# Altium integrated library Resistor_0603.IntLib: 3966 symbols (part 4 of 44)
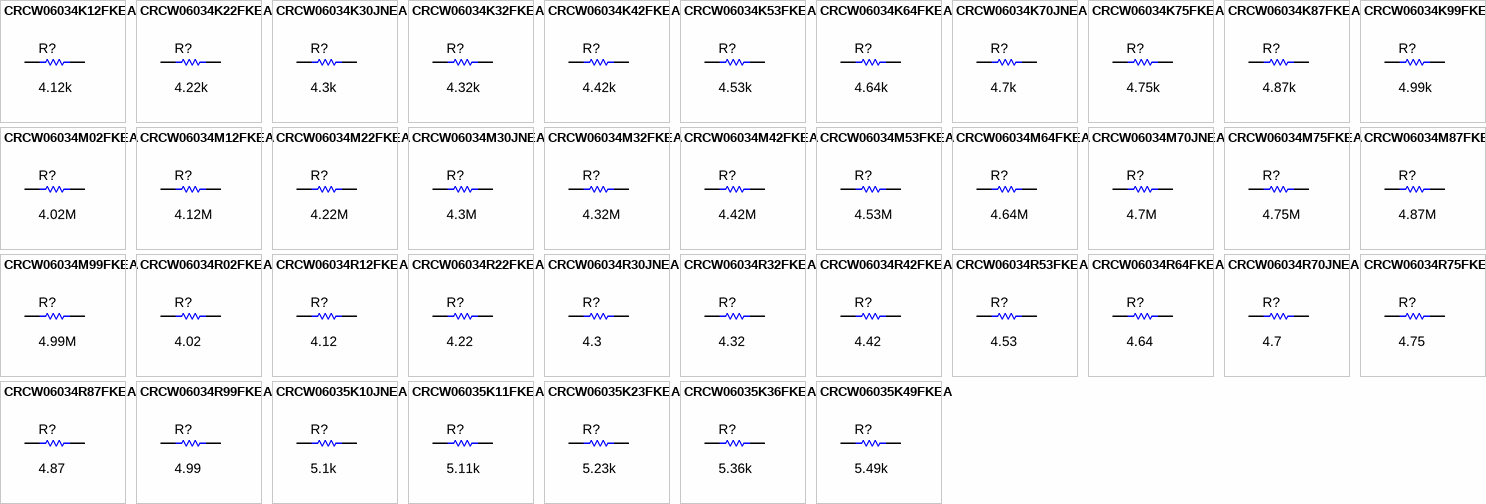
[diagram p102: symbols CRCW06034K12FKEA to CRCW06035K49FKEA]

## CRCW06034R42FKEA
designator R?  ValueDisplayed: 4.42  (hidden comment: CRCW06034R42FKEA)
RES, 4.42, 1%, 0.1 W, 0603; Manufacturer: Vishay-Dale; CompType: Resistor; Value: 4.42; Value_Code: 4R42; Tolerance_%: 1; Power_W: 0.1; Value2: 0.1W; VDC_V: 75; TempCo: 100 ppm/C; SizeArea_mm2: 1.28; SizeX_mm: 1.6; SizeY_mm: 0.8; EIA_Code: E96; U/M: EA; AEC Category: Q200
signal-integrity model Resistor
simulation model Resistor
footprint 0603
footprint 0603M
footprint 0603L
footprint 0603_HV
footprint 0603S
pins: 1, 2

## CRCW06034R53FKEA
designator R?  ValueDisplayed: 4.53  (hidden comment: CRCW06034R53FKEA)
RES, 4.53, 1%, 0.1 W, 0603; Manufacturer: Vishay-Dale; CompType: Resistor; Value: 4.53; Value_Code: 4R53; Tolerance_%: 1; Power_W: 0.1; Value2: 0.1W; VDC_V: 75; TempCo: 100 ppm/C; SizeArea_mm2: 1.28; SizeX_mm: 1.6; SizeY_mm: 0.8; EIA_Code: E96; U/M: EA; AEC Category: Q200
signal-integrity model Resistor
simulation model Resistor
footprint 0603
footprint 0603M
footprint 0603L
footprint 0603_HV
footprint 0603S
pins: 1, 2

## CRCW06034R64FKEA
designator R?  ValueDisplayed: 4.64  (hidden comment: CRCW06034R64FKEA)
RES, 4.64, 1%, 0.1 W, 0603; Manufacturer: Vishay-Dale; CompType: Resistor; Value: 4.64; Value_Code: 4R64; Tolerance_%: 1; Power_W: 0.1; Value2: 0.1W; VDC_V: 75; TempCo: 100 ppm/C; SizeArea_mm2: 1.28; SizeX_mm: 1.6; SizeY_mm: 0.8; EIA_Code: E96; U/M: EA; AEC Category: Q200
signal-integrity model Resistor
simulation model Resistor
footprint 0603
footprint 0603M
footprint 0603L
footprint 0603_HV
footprint 0603S
pins: 1, 2

## CRCW06034R70JNEA
designator R?  ValueDisplayed: 4.7  (hidden comment: CRCW06034R70JNEA)
RES, 4.7, 5%, 0.1 W, 0603; Manufacturer: Vishay-Dale; CompType: Resistor; Value: 4.7; Value_Code: 4R70; Tolerance_%: 5; Power_W: 0.1; Value2: 0.1W; VDC_V: 75; TempCo: 200 ppm/C; SizeArea_mm2: 1.28; SizeX_mm: 1.6; SizeY_mm: 0.8; SizeZ_mm: 1; EIA_Code: E24; U/M: EA; AEC Category: Q200; Green_Lifecycle: Active; Green_REACh: Passed
signal-integrity model Resistor
simulation model Resistor
footprint 0603
footprint 0603M
footprint 0603L
footprint 0603_HV
footprint 0603S
pins: 1, 2

## CRCW06034R75FKEA
designator R?  ValueDisplayed: 4.75  (hidden comment: CRCW06034R75FKEA)
RES, 4.75, 1%, 0.1 W, 0603; Manufacturer: Vishay-Dale; CompType: Resistor; Value: 4.75; Value_Code: 4R75; Tolerance_%: 1; Power_W: 0.1; Value2: 0.1W; VDC_V: 75; TempCo: 100 ppm/C; SizeArea_mm2: 1.28; SizeX_mm: 1.6; SizeY_mm: 0.8; EIA_Code: E96; U/M: EA; AEC Category: Q200; Green_Lifecycle: Active; Green_REACh: Passed
signal-integrity model Resistor
simulation model Resistor
footprint 0603
footprint 0603M
footprint 0603L
footprint 0603_HV
footprint 0603S
pins: 1, 2

## CRCW06034R87FKEA
designator R?  ValueDisplayed: 4.87  (hidden comment: CRCW06034R87FKEA)
RES, 4.87, 1%, 0.1 W, 0603; Manufacturer: Vishay-Dale; CompType: Resistor; Value: 4.87; Value_Code: 4R87; Tolerance_%: 1; Power_W: 0.1; Value2: 0.1W; VDC_V: 75; TempCo: 100 ppm/C; SizeArea_mm2: 1.28; SizeX_mm: 1.6; SizeY_mm: 0.8; EIA_Code: E96; U/M: EA; AEC Category: Q200; Green_Lifecycle: Active; Green_REACh: Passed
signal-integrity model Resistor
simulation model Resistor
footprint 0603
footprint 0603M
footprint 0603L
footprint 0603_HV
footprint 0603S
pins: 1, 2

## CRCW06034R99FKEA
designator R?  ValueDisplayed: 4.99  (hidden comment: CRCW06034R99FKEA)
RES, 4.99, 1%, 0.1 W, 0603; Manufacturer: Vishay-Dale; CompType: Resistor; Value: 4.99; Value_Code: 4R99; Tolerance_%: 1; Power_W: 0.1; Value2: 0.1W; VDC_V: 75; TempCo: 100 ppm/C; SizeArea_mm2: 1.28; SizeX_mm: 1.6; SizeY_mm: 0.8; EIA_Code: E96; U/M: EA; AEC Category: Q200; Green_Lifecycle: Active; Green_REACh: Passed
signal-integrity model Resistor
simulation model Resistor
footprint 0603
footprint 0603M
footprint 0603L
footprint 0603_HV
footprint 0603S
pins: 1, 2

## CRCW06035K10JNEA
designator R?  ValueDisplayed: 5.1k  (hidden comment: CRCW06035K10JNEA)
RES, 5.1 k, 5%, 0.1 W, 0603; Manufacturer: Vishay-Dale; CompType: Resistor; Value: 5.1k; Res_ohm: 5100; Value_Code: 5k10; Tolerance_%: 5; Power_W: 0.1; Value2: 0.1W; VDC_V: 75; TempCo: 200 ppm/C; SizeArea_mm2: 1.28; SizeX_mm: 1.6; SizeY_mm: 0.8; SizeZ_mm: 1; EIA_Code: E24; U/M: EA; AEC Category: Q200; Green_Lifecycle: Active; Green_REACh: Passed
signal-integrity model Resistor
simulation model Resistor
footprint 0603
footprint 0603M
footprint 0603L
footprint 0603_HV
footprint 0603S
pins: 1, 2

## CRCW06035K11FKEA
designator R?  ValueDisplayed: 5.11k  (hidden comment: CRCW06035K11FKEA)
RES, 5.11 k, 1%, 0.1 W, 0603; Manufacturer: Vishay-Dale; CompType: Resistor; Value: 5.11k; Res_ohm: 5110; Value_Code: 5k11; Tolerance_%: 1; Power_W: 0.1; Value2: 0.1W; VDC_V: 75; TempCo: 100 ppm/C; SizeArea_mm2: 1.28; SizeX_mm: 1.6; SizeY_mm: 0.8; EIA_Code: E96; U/M: EA; AEC Category: Q200; Green_Lifecycle: Active; Green_REACh: Passed
signal-integrity model Resistor
simulation model Resistor
footprint 0603
footprint 0603M
footprint 0603L
footprint 0603_HV
footprint 0603S
pins: 1, 2

## CRCW06035K23FKEA
designator R?  ValueDisplayed: 5.23k  (hidden comment: CRCW06035K23FKEA)
RES, 5.23 k, 1%, 0.1 W, 0603; Manufacturer: Vishay-Dale; CompType: Resistor; Value: 5.23k; Res_ohm: 5230; Value_Code: 5k23; Tolerance_%: 1; Power_W: 0.1; Value2: 0.1W; VDC_V: 75; TempCo: 100 ppm/C; SizeArea_mm2: 1.28; SizeX_mm: 1.6; SizeY_mm: 0.8; EIA_Code: E96; U/M: EA; AEC Category: Q200; Green_Lifecycle: Active; Green_REACh: Passed
signal-integrity model Resistor
simulation model Resistor
footprint 0603
footprint 0603M
footprint 0603L
footprint 0603_HV
footprint 0603S
pins: 1, 2

## CRCW06035K36FKEA
designator R?  ValueDisplayed: 5.36k  (hidden comment: CRCW06035K36FKEA)
RES, 5.36 k, 1%, 0.1 W, 0603; Manufacturer: Vishay-Dale; CompType: Resistor; Value: 5.36k; Res_ohm: 5360; Value_Code: 5k36; Tolerance_%: 1; Power_W: 0.1; Value2: 0.1W; VDC_V: 75; TempCo: 100 ppm/C; SizeArea_mm2: 1.28; SizeX_mm: 1.6; SizeY_mm: 0.8; EIA_Code: E96; U/M: EA; AEC Category: Q200; Green_Lifecycle: Active; Green_REACh: Passed
signal-integrity model Resistor
simulation model Resistor
footprint 0603
footprint 0603M
footprint 0603L
footprint 0603_HV
footprint 0603S
pins: 1, 2

## CRCW06035K49FKEA
designator R?  ValueDisplayed: 5.49k  (hidden comment: CRCW06035K49FKEA)
RES, 5.49 k, 1%, 0.1 W, 0603; Manufacturer: Vishay-Dale; CompType: Resistor; Value: 5.49k; Res_ohm: 5490; Value_Code: 5k49; Tolerance_%: 1; Power_W: 0.1; Value2: 0.1W; VDC_V: 75; TempCo: 100 ppm/C; SizeArea_mm2: 1.28; SizeX_mm: 1.6; SizeY_mm: 0.8; EIA_Code: E96; U/M: EA; AEC Category: Q200; Green_Lifecycle: Active; Green_REACh: Passed
signal-integrity model Resistor
simulation model Resistor
footprint 0603
footprint 0603M
footprint 0603L
footprint 0603_HV
footprint 0603S
pins: 1, 2

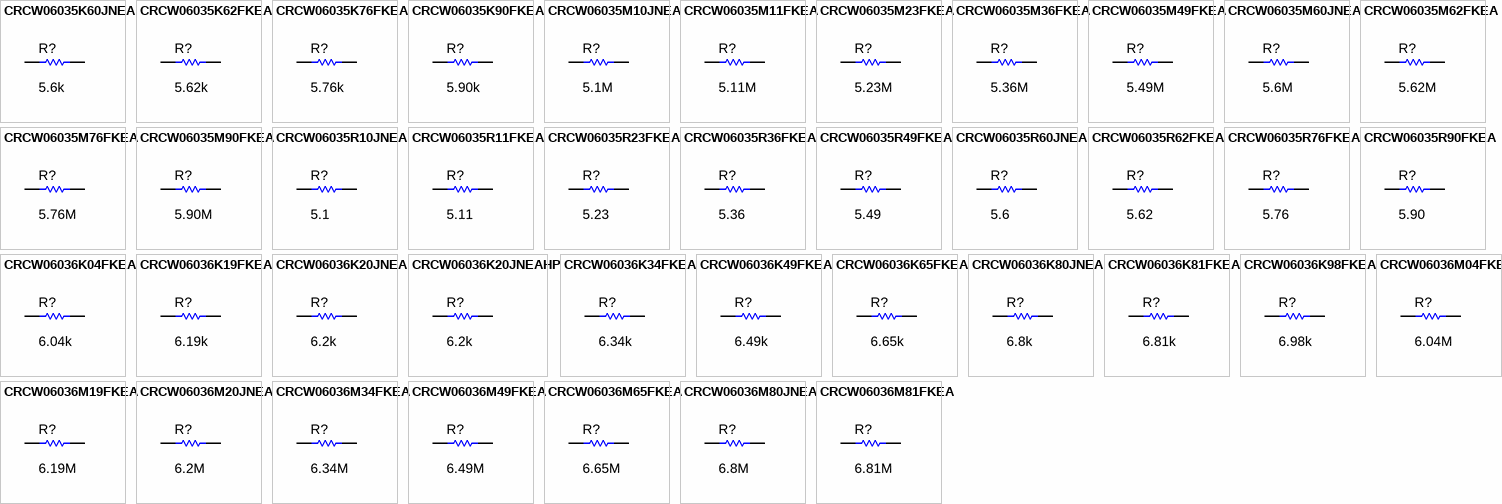
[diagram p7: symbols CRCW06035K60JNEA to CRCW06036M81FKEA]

## CRCW06035K60JNEA
designator R?  ValueDisplayed: 5.6k  (hidden comment: CRCW06035K60JNEA)
RES, 5.6 k, 5%, 0.1 W, 0603; Manufacturer: Vishay-Dale; CompType: Resistor; Value: 5.6k; Res_ohm: 5600; Value_Code: 5k60; Tolerance_%: 5; Power_W: 0.1; Value2: 0.1W; VDC_V: 75; TempCo: 200 ppm/C; SizeArea_mm2: 1.28; SizeX_mm: 1.6; SizeY_mm: 0.8; SizeZ_mm: 1; EIA_Code: E24; U/M: EA; AEC Category: Q200; Green_Lifecycle: Active; Green_REACh: Passed
signal-integrity model Resistor
simulation model Resistor
footprint 0603
footprint 0603M
footprint 0603L
footprint 0603_HV
footprint 0603S
pins: 1, 2

## CRCW06035K62FKEA
designator R?  ValueDisplayed: 5.62k  (hidden comment: CRCW06035K62FKEA)
RES, 5.62 k, 1%, 0.1 W, 0603; Manufacturer: Vishay-Dale; CompType: Resistor; Value: 5.62k; Res_ohm: 5620; Value_Code: 5k62; Tolerance_%: 1; Power_W: 0.1; Value2: 0.1W; VDC_V: 75; TempCo: 100 ppm/C; SizeArea_mm2: 1.28; SizeX_mm: 1.6; SizeY_mm: 0.8; EIA_Code: E96; U/M: EA; AEC Category: Q200; Green_Lifecycle: Active; Green_REACh: Passed
signal-integrity model Resistor
simulation model Resistor
footprint 0603
footprint 0603M
footprint 0603L
footprint 0603_HV
footprint 0603S
pins: 1, 2

## CRCW06035K76FKEA
designator R?  ValueDisplayed: 5.76k  (hidden comment: CRCW06035K76FKEA)
RES, 5.76 k, 1%, 0.1 W, 0603; Manufacturer: Vishay-Dale; CompType: Resistor; Value: 5.76k; Res_ohm: 5760; Value_Code: 5k76; Tolerance_%: 1; Power_W: 0.1; Value2: 0.1W; VDC_V: 75; TempCo: 100 ppm/C; SizeArea_mm2: 1.28; SizeX_mm: 1.6; SizeY_mm: 0.8; EIA_Code: E96; U/M: EA; AEC Category: Q200; Green_Lifecycle: Active; Green_REACh: Passed
signal-integrity model Resistor
simulation model Resistor
footprint 0603
footprint 0603M
footprint 0603L
footprint 0603_HV
footprint 0603S
pins: 1, 2

## CRCW06035K90FKEA
designator R?  ValueDisplayed: 5.90k  (hidden comment: CRCW06035K90FKEA)
RES, 5.90 k, 1%, 0.1 W, 0603; Manufacturer: Vishay-Dale; CompType: Resistor; Value: 5.90k; Res_ohm: 5900; Value_Code: 5k90; Tolerance_%: 1; Power_W: 0.1; Value2: 0.1W; VDC_V: 75; TempCo: 100 ppm/C; SizeArea_mm2: 1.28; SizeX_mm: 1.6; SizeY_mm: 0.8; EIA_Code: E96; U/M: EA; AEC Category: Q200; Green_Lifecycle: Active; Green_REACh: Passed
signal-integrity model Resistor
simulation model Resistor
footprint 0603
footprint 0603M
footprint 0603L
footprint 0603_HV
footprint 0603S
pins: 1, 2

## CRCW06035M10JNEA
designator R?  ValueDisplayed: 5.1M  (hidden comment: CRCW06035M10JNEA)
RES, 5.1 M, 5%, 0.1 W, 0603; Manufacturer: Vishay-Dale; CompType: Resistor; Value: 5.1Meg; Res_ohm: 5100000; Value_Code: 5M10; Tolerance_%: 5; Power_W: 0.1; Value2: 0.1W; VDC_V: 75; TempCo: 200 ppm/C; SizeArea_mm2: 1.28; SizeX_mm: 1.6; SizeY_mm: 0.8; SizeZ_mm: 1; EIA_Code: E24; U/M: EA; AEC Category: Q200
signal-integrity model Resistor
simulation model Resistor
footprint 0603
footprint 0603M
footprint 0603L
footprint 0603_HV
footprint 0603S
pins: 1, 2

## CRCW06035M11FKEA
designator R?  ValueDisplayed: 5.11M  (hidden comment: CRCW06035M11FKEA)
RES, 5.11 M, 1%, 0.1 W, 0603; Manufacturer: Vishay-Dale; CompType: Resistor; Value: 5.11Meg; Res_ohm: 5110000; Value_Code: 5M11; Tolerance_%: 1; Power_W: 0.1; Value2: 0.1W; VDC_V: 75; TempCo: 100 ppm/C; SizeArea_mm2: 1.28; SizeX_mm: 1.6; SizeY_mm: 0.8; EIA_Code: E96; U/M: EA; AEC Category: Q200
signal-integrity model Resistor
simulation model Resistor
footprint 0603
footprint 0603M
footprint 0603L
footprint 0603_HV
footprint 0603S
pins: 1, 2

## CRCW06035M23FKEA
designator R?  ValueDisplayed: 5.23M  (hidden comment: CRCW06035M23FKEA)
RES, 5.23 M, 1%, 0.1 W, 0603; Manufacturer: Vishay-Dale; CompType: Resistor; Value: 5.23Meg; Res_ohm: 5230000; Value_Code: 5M23; Tolerance_%: 1; Power_W: 0.1; Value2: 0.1W; VDC_V: 75; TempCo: 100 ppm/C; SizeArea_mm2: 1.28; SizeX_mm: 1.6; SizeY_mm: 0.8; EIA_Code: E96; U/M: EA; AEC Category: Q200
signal-integrity model Resistor
simulation model Resistor
footprint 0603
footprint 0603M
footprint 0603L
footprint 0603_HV
footprint 0603S
pins: 1, 2

## CRCW06035M36FKEA
designator R?  ValueDisplayed: 5.36M  (hidden comment: CRCW06035M36FKEA)
RES, 5.36 M, 1%, 0.1 W, 0603; Manufacturer: Vishay-Dale; CompType: Resistor; Value: 5.36Meg; Res_ohm: 5360000; Value_Code: 5M36; Tolerance_%: 1; Power_W: 0.1; Value2: 0.1W; VDC_V: 75; TempCo: 100 ppm/C; SizeArea_mm2: 1.28; SizeX_mm: 1.6; SizeY_mm: 0.8; EIA_Code: E96; U/M: EA; AEC Category: Q200; Green_Lifecycle: Active; Green_REACh: Passed
signal-integrity model Resistor
simulation model Resistor
footprint 0603
footprint 0603M
footprint 0603L
footprint 0603_HV
footprint 0603S
pins: 1, 2

## CRCW06035M49FKEA
designator R?  ValueDisplayed: 5.49M  (hidden comment: CRCW06035M49FKEA)
RES, 5.49 M, 1%, 0.1 W, 0603; Manufacturer: Vishay-Dale; CompType: Resistor; Value: 5.49Meg; Res_ohm: 5490000; Value_Code: 5M49; Tolerance_%: 1; Power_W: 0.1; Value2: 0.1W; VDC_V: 75; TempCo: 100 ppm/C; SizeArea_mm2: 1.28; SizeX_mm: 1.6; SizeY_mm: 0.8; EIA_Code: E96; U/M: EA; AEC Category: Q200; Green_Lifecycle: Active; Green_REACh: Passed
signal-integrity model Resistor
simulation model Resistor
footprint 0603
footprint 0603M
footprint 0603L
footprint 0603_HV
footprint 0603S
pins: 1, 2

## CRCW06035M60JNEA
designator R?  ValueDisplayed: 5.6M  (hidden comment: CRCW06035M60JNEA)
RES, 5.6 M, 5%, 0.1 W, 0603; Manufacturer: Vishay-Dale; CompType: Resistor; Value: 5.6Meg; Res_ohm: 5600000; Value_Code: 5M60; Tolerance_%: 5; Power_W: 0.1; Value2: 0.1W; VDC_V: 75; TempCo: 200 ppm/C; SizeArea_mm2: 1.28; SizeX_mm: 1.6; SizeY_mm: 0.8; SizeZ_mm: 1; EIA_Code: E24; U/M: EA; AEC Category: Q200
signal-integrity model Resistor
simulation model Resistor
footprint 0603
footprint 0603M
footprint 0603L
footprint 0603_HV
footprint 0603S
pins: 1, 2

## CRCW06035M62FKEA
designator R?  ValueDisplayed: 5.62M  (hidden comment: CRCW06035M62FKEA)
RES, 5.62 M, 1%, 0.1 W, 0603; Manufacturer: Vishay-Dale; CompType: Resistor; Value: 5.62Meg; Res_ohm: 5620000; Value_Code: 5M62; Tolerance_%: 1; Power_W: 0.1; Value2: 0.1W; VDC_V: 75; TempCo: 100 ppm/C; SizeArea_mm2: 1.28; SizeX_mm: 1.6; SizeY_mm: 0.8; EIA_Code: E96; U/M: EA; AEC Category: Q200; Green_Lifecycle: Active; Green_REACh: Passed
signal-integrity model Resistor
simulation model Resistor
footprint 0603
footprint 0603M
footprint 0603L
footprint 0603_HV
footprint 0603S
pins: 1, 2

## CRCW06035M76FKEA
designator R?  ValueDisplayed: 5.76M  (hidden comment: CRCW06035M76FKEA)
RES, 5.76 M, 1%, 0.1 W, 0603; Manufacturer: Vishay-Dale; CompType: Resistor; Value: 5.76Meg; Res_ohm: 5760000; Value_Code: 5M76; Tolerance_%: 1; Power_W: 0.1; Value2: 0.1W; VDC_V: 75; TempCo: 100 ppm/C; SizeArea_mm2: 1.28; SizeX_mm: 1.6; SizeY_mm: 0.8; EIA_Code: E96; U/M: EA; AEC Category: Q200; Green_Lifecycle: Active; Green_REACh: Passed
signal-integrity model Resistor
simulation model Resistor
footprint 0603
footprint 0603M
footprint 0603L
footprint 0603_HV
footprint 0603S
pins: 1, 2

## CRCW06035M90FKEA
designator R?  ValueDisplayed: 5.90M  (hidden comment: CRCW06035M90FKEA)
RES, 5.90 M, 1%, 0.1 W, 0603; Manufacturer: Vishay-Dale; CompType: Resistor; Value: 5.90Meg; Res_ohm: 5900000; Value_Code: 5M90; Tolerance_%: 1; Power_W: 0.1; Value2: 0.1W; VDC_V: 75; TempCo: 100 ppm/C; SizeArea_mm2: 1.28; SizeX_mm: 1.6; SizeY_mm: 0.8; EIA_Code: E96; U/M: EA; AEC Category: Q200
signal-integrity model Resistor
simulation model Resistor
footprint 0603
footprint 0603M
footprint 0603L
footprint 0603_HV
footprint 0603S
pins: 1, 2

## CRCW06035R10JNEA
designator R?  ValueDisplayed: 5.1  (hidden comment: CRCW06035R10JNEA)
RES, 5.1, 5%, 0.1 W, 0603; Manufacturer: Vishay-Dale; CompType: Resistor; Value: 5.1; Value_Code: 5R10; Tolerance_%: 5; Power_W: 0.1; Value2: 0.1W; VDC_V: 75; TempCo: 200 ppm/C; SizeArea_mm2: 1.28; SizeX_mm: 1.6; SizeY_mm: 0.8; SizeZ_mm: 1; EIA_Code: E24; U/M: EA; AEC Category: Q200; Green_Lifecycle: Active; Green_REACh: Passed
signal-integrity model Resistor
simulation model Resistor
footprint 0603
footprint 0603M
footprint 0603L
footprint 0603_HV
footprint 0603S
pins: 1, 2

## CRCW06035R11FKEA
designator R?  ValueDisplayed: 5.11  (hidden comment: CRCW06035R11FKEA)
RES, 5.11, 1%, 0.1 W, 0603; Manufacturer: Vishay-Dale; CompType: Resistor; Value: 5.11; Value_Code: 5R11; Tolerance_%: 1; Power_W: 0.1; Value2: 0.1W; VDC_V: 75; TempCo: 100 ppm/C; SizeArea_mm2: 1.28; SizeX_mm: 1.6; SizeY_mm: 0.8; EIA_Code: E96; U/M: EA; AEC Category: Q200; Green_Lifecycle: Active; Green_REACh: Passed
signal-integrity model Resistor
simulation model Resistor
footprint 0603
footprint 0603M
footprint 0603L
footprint 0603_HV
footprint 0603S
pins: 1, 2

## CRCW06035R23FKEA
designator R?  ValueDisplayed: 5.23  (hidden comment: CRCW06035R23FKEA)
RES, 5.23, 1%, 0.1 W, 0603; Manufacturer: Vishay-Dale; CompType: Resistor; Value: 5.23; Value_Code: 5R23; Tolerance_%: 1; Power_W: 0.1; Value2: 0.1W; VDC_V: 75; TempCo: 100 ppm/C; SizeArea_mm2: 1.28; SizeX_mm: 1.6; SizeY_mm: 0.8; EIA_Code: E96; U/M: EA; AEC Category: Q200
signal-integrity model Resistor
simulation model Resistor
footprint 0603
footprint 0603M
footprint 0603L
footprint 0603_HV
footprint 0603S
pins: 1, 2

## CRCW06035R36FKEA
designator R?  ValueDisplayed: 5.36  (hidden comment: CRCW06035R36FKEA)
RES, 5.36, 1%, 0.1 W, 0603; Manufacturer: Vishay-Dale; CompType: Resistor; Value: 5.36; Value_Code: 5R36; Tolerance_%: 1; Power_W: 0.1; Value2: 0.1W; VDC_V: 75; TempCo: 100 ppm/C; SizeArea_mm2: 1.28; SizeX_mm: 1.6; SizeY_mm: 0.8; EIA_Code: E96; U/M: EA; AEC Category: Q200
signal-integrity model Resistor
simulation model Resistor
footprint 0603
footprint 0603M
footprint 0603L
footprint 0603_HV
footprint 0603S
pins: 1, 2

## CRCW06035R49FKEA
designator R?  ValueDisplayed: 5.49  (hidden comment: CRCW06035R49FKEA)
RES, 5.49, 1%, 0.1 W, 0603; Manufacturer: Vishay-Dale; CompType: Resistor; Value: 5.49; Value_Code: 5R49; Tolerance_%: 1; Power_W: 0.1; Value2: 0.1W; VDC_V: 75; TempCo: 100 ppm/C; SizeArea_mm2: 1.28; SizeX_mm: 1.6; SizeY_mm: 0.8; EIA_Code: E96; U/M: EA; AEC Category: Q200
signal-integrity model Resistor
simulation model Resistor
footprint 0603
footprint 0603M
footprint 0603L
footprint 0603_HV
footprint 0603S
pins: 1, 2

## CRCW06035R60JNEA
designator R?  ValueDisplayed: 5.6  (hidden comment: CRCW06035R60JNEA)
RES, 5.6, 5%, 0.1 W, 0603; Manufacturer: Vishay-Dale; CompType: Resistor; Value: 5.6; Value_Code: 5R60; Tolerance_%: 5; Power_W: 0.1; Value2: 0.1W; VDC_V: 75; TempCo: 200 ppm/C; SizeArea_mm2: 1.28; SizeX_mm: 1.6; SizeY_mm: 0.8; SizeZ_mm: 1; EIA_Code: E24; U/M: EA; AEC Category: Q200; Green_Lifecycle: Active; Green_REACh: Passed
signal-integrity model Resistor
simulation model Resistor
footprint 0603
footprint 0603M
footprint 0603L
footprint 0603_HV
footprint 0603S
pins: 1, 2

## CRCW06035R62FKEA
designator R?  ValueDisplayed: 5.62  (hidden comment: CRCW06035R62FKEA)
RES, 5.62, 1%, 0.1 W, 0603; Manufacturer: Vishay-Dale; CompType: Resistor; Value: 5.62; Value_Code: 5R62; Tolerance_%: 1; Power_W: 0.1; Value2: 0.1W; VDC_V: 75; TempCo: 100 ppm/C; SizeArea_mm2: 1.28; SizeX_mm: 1.6; SizeY_mm: 0.8; EIA_Code: E96; U/M: EA; AEC Category: Q200
signal-integrity model Resistor
simulation model Resistor
footprint 0603
footprint 0603M
footprint 0603L
footprint 0603_HV
footprint 0603S
pins: 1, 2

## CRCW06035R76FKEA
designator R?  ValueDisplayed: 5.76  (hidden comment: CRCW06035R76FKEA)
RES, 5.76, 1%, 0.1 W, 0603; Manufacturer: Vishay-Dale; CompType: Resistor; Value: 5.76; Value_Code: 5R76; Tolerance_%: 1; Power_W: 0.1; Value2: 0.1W; VDC_V: 75; TempCo: 100 ppm/C; SizeArea_mm2: 1.28; SizeX_mm: 1.6; SizeY_mm: 0.8; EIA_Code: E96; U/M: EA; AEC Category: Q200
signal-integrity model Resistor
simulation model Resistor
footprint 0603
footprint 0603M
footprint 0603L
footprint 0603_HV
footprint 0603S
pins: 1, 2

## CRCW06035R90FKEA
designator R?  ValueDisplayed: 5.90  (hidden comment: CRCW06035R90FKEA)
RES, 5.90, 1%, 0.1 W, 0603; Manufacturer: Vishay-Dale; CompType: Resistor; Value: 5.90; Res_ohm: 5.9; Value_Code: 5R90; Tolerance_%: 1; Power_W: 0.1; Value2: 0.1W; VDC_V: 75; TempCo: 100 ppm/C; SizeArea_mm2: 1.28; SizeX_mm: 1.6; SizeY_mm: 0.8; EIA_Code: E96; U/M: EA; AEC Category: Q200
signal-integrity model Resistor
simulation model Resistor
footprint 0603
footprint 0603M
footprint 0603L
footprint 0603_HV
footprint 0603S
pins: 1, 2

## CRCW06036K04FKEA
designator R?  ValueDisplayed: 6.04k  (hidden comment: CRCW06036K04FKEA)
RES, 6.04 k, 1%, 0.1 W, 0603; Manufacturer: Vishay-Dale; CompType: Resistor; Value: 6.04k; Res_ohm: 6040; Value_Code: 6k04; Tolerance_%: 1; Power_W: 0.1; Value2: 0.1W; VDC_V: 75; TempCo: 100 ppm/C; SizeArea_mm2: 1.28; SizeX_mm: 1.6; SizeY_mm: 0.8; EIA_Code: E96; U/M: EA; AEC Category: Q200; Green_Lifecycle: Active; Green_REACh: Passed
signal-integrity model Resistor
simulation model Resistor
footprint 0603
footprint 0603M
footprint 0603L
footprint 0603_HV
footprint 0603S
pins: 1, 2

## CRCW06036K19FKEA
designator R?  ValueDisplayed: 6.19k  (hidden comment: CRCW06036K19FKEA)
RES, 6.19 k, 1%, 0.1 W, 0603; Manufacturer: Vishay-Dale; CompType: Resistor; Value: 6.19k; Res_ohm: 6190; Value_Code: 6k19; Tolerance_%: 1; Power_W: 0.1; Value2: 0.1W; VDC_V: 75; TempCo: 100 ppm/C; SizeArea_mm2: 1.28; SizeX_mm: 1.6; SizeY_mm: 0.8; EIA_Code: E96; U/M: EA; AEC Category: Q200; Green_Lifecycle: Active; Green_REACh: Passed
signal-integrity model Resistor
simulation model Resistor
footprint 0603
footprint 0603M
footprint 0603L
footprint 0603_HV
footprint 0603S
pins: 1, 2

## CRCW06036K20JNEA
designator R?  ValueDisplayed: 6.2k  (hidden comment: CRCW06036K20JNEA)
RES, 6.2 k, 5%, 0.1 W, 0603; Manufacturer: Vishay-Dale; CompType: Resistor; Value: 6.2k; Res_ohm: 6200; Value_Code: 6k20; Tolerance_%: 5; Power_W: 0.1; Value2: 0.1W; VDC_V: 75; TempCo: 200 ppm/C; SizeArea_mm2: 1.28; SizeX_mm: 1.6; SizeY_mm: 0.8; SizeZ_mm: 1; EIA_Code: E24; U/M: EA; AEC Category: Q200; Green_Lifecycle: Active; Green_REACh: Passed
signal-integrity model Resistor
simulation model Resistor
footprint 0603
footprint 0603M
footprint 0603L
footprint 0603_HV
footprint 0603S
pins: 1, 2

## CRCW06036K20JNEAHP
designator R?  ValueDisplayed: 6.2k  (hidden comment: CRCW06036K20JNEAHP)
RES, 6.2 k, 5%, 0.25 W, 0603; Manufacturer: Vishay-Dale; CompType: Resistor; Value: 6.2k; Res_ohm: 6200; Value_Code: 6k20; Tolerance_%: 5; Power_W: 0.25; Value2: 0.25W; VDC_V: 75; TempCo: 200 ppm/C; SizeArea_mm2: 1.28; SizeX_mm: 1.6; SizeY_mm: 0.8; SizeZ_mm: 1; EIA_Code: E24; U/M: EA; AEC Category: Q200
signal-integrity model Resistor
simulation model Resistor
footprint 0603
footprint 0603M
footprint 0603L
footprint 0603_HV
footprint 0603S
pins: 1, 2

## CRCW06036K34FKEA
designator R?  ValueDisplayed: 6.34k  (hidden comment: CRCW06036K34FKEA)
RES, 6.34 k, 1%, 0.1 W, 0603; Manufacturer: Vishay-Dale; CompType: Resistor; Value: 6.34k; Res_ohm: 6340; Value_Code: 6k34; Tolerance_%: 1; Power_W: 0.1; Value2: 0.1W; VDC_V: 75; TempCo: 100 ppm/C; SizeArea_mm2: 1.28; SizeX_mm: 1.6; SizeY_mm: 0.8; EIA_Code: E96; U/M: EA; AEC Category: Q200; Green_Lifecycle: Active; Green_REACh: Passed
signal-integrity model Resistor
simulation model Resistor
footprint 0603
footprint 0603M
footprint 0603L
footprint 0603_HV
footprint 0603S
pins: 1, 2

## CRCW06036K49FKEA
designator R?  ValueDisplayed: 6.49k  (hidden comment: CRCW06036K49FKEA)
RES, 6.49 k, 1%, 0.1 W, 0603; Manufacturer: Vishay-Dale; CompType: Resistor; Value: 6.49k; Res_ohm: 6490; Value_Code: 6k49; Tolerance_%: 1; Power_W: 0.1; Value2: 0.1W; VDC_V: 75; TempCo: 100 ppm/C; SizeArea_mm2: 1.28; SizeX_mm: 1.6; SizeY_mm: 0.8; EIA_Code: E96; U/M: EA; AEC Category: Q200; Green_Lifecycle: Active; Green_REACh: Passed
signal-integrity model Resistor
simulation model Resistor
footprint 0603
footprint 0603M
footprint 0603L
footprint 0603_HV
footprint 0603S
pins: 1, 2

## CRCW06036K65FKEA
designator R?  ValueDisplayed: 6.65k  (hidden comment: CRCW06036K65FKEA)
RES, 6.65 k, 1%, 0.1 W, 0603; Manufacturer: Vishay-Dale; CompType: Resistor; Value: 6.65k; Res_ohm: 6650; Value_Code: 6k65; Tolerance_%: 1; Power_W: 0.1; Value2: 0.1W; VDC_V: 75; TempCo: 100 ppm/C; SizeArea_mm2: 1.28; SizeX_mm: 1.6; SizeY_mm: 0.8; EIA_Code: E96; U/M: EA; AEC Category: Q200
signal-integrity model Resistor
simulation model Resistor
footprint 0603
footprint 0603M
footprint 0603L
footprint 0603_HV
footprint 0603S
pins: 1, 2

## CRCW06036K80JNEA
designator R?  ValueDisplayed: 6.8k  (hidden comment: CRCW06036K80JNEA)
RES, 6.8 k, 5%, 0.1 W, 0603; Manufacturer: Vishay-Dale; CompType: Resistor; Value: 6.8k; Res_ohm: 6800; Value_Code: 6k80; Tolerance_%: 5; Power_W: 0.1; Value2: 0.1W; VDC_V: 75; TempCo: 200 ppm/C; SizeArea_mm2: 1.28; SizeX_mm: 1.6; SizeY_mm: 0.8; SizeZ_mm: 1; EIA_Code: E24; U/M: EA; AEC Category: Q200
signal-integrity model Resistor
simulation model Resistor
footprint 0603
footprint 0603M
footprint 0603L
footprint 0603_HV
footprint 0603S
pins: 1, 2

## CRCW06036K81FKEA
designator R?  ValueDisplayed: 6.81k  (hidden comment: CRCW06036K81FKEA)
RES, 6.81 k, 1%, 0.1 W, 0603; Manufacturer: Vishay-Dale; CompType: Resistor; Value: 6.81k; Res_ohm: 6810; Value_Code: 6k81; Tolerance_%: 1; Power_W: 0.1; Value2: 0.1W; VDC_V: 75; TempCo: 100 ppm/C; SizeArea_mm2: 1.28; SizeX_mm: 1.6; SizeY_mm: 0.8; EIA_Code: E96; U/M: EA; AEC Category: Q200; Green_Lifecycle: Active; Green_REACh: Passed
signal-integrity model Resistor
simulation model Resistor
footprint 0603
footprint 0603M
footprint 0603L
footprint 0603_HV
footprint 0603S
pins: 1, 2

## CRCW06036K98FKEA
designator R?  ValueDisplayed: 6.98k  (hidden comment: CRCW06036K98FKEA)
RES, 6.98 k, 1%, 0.1 W, 0603; Manufacturer: Vishay-Dale; CompType: Resistor; Value: 6.98k; Res_ohm: 6980; Value_Code: 6k98; Tolerance_%: 1; Power_W: 0.1; Value2: 0.1W; VDC_V: 75; TempCo: 100 ppm/C; SizeArea_mm2: 1.28; SizeX_mm: 1.6; SizeY_mm: 0.8; EIA_Code: E96; U/M: EA; AEC Category: Q200; Green_Lifecycle: Active; Green_REACh: Passed
signal-integrity model Resistor
simulation model Resistor
footprint 0603
footprint 0603M
footprint 0603L
footprint 0603_HV
footprint 0603S
pins: 1, 2

## CRCW06036M04FKEA
designator R?  ValueDisplayed: 6.04M  (hidden comment: CRCW06036M04FKEA)
RES, 6.04 M, 1%, 0.1 W, 0603; Manufacturer: Vishay-Dale; CompType: Resistor; Value: 6.04Meg; Res_ohm: 6040000; Value_Code: 6M04; Tolerance_%: 1; Power_W: 0.1; Value2: 0.1W; VDC_V: 75; TempCo: 100 ppm/C; SizeArea_mm2: 1.28; SizeX_mm: 1.6; SizeY_mm: 0.8; EIA_Code: E96; U/M: EA; AEC Category: Q200
signal-integrity model Resistor
simulation model Resistor
footprint 0603
footprint 0603M
footprint 0603L
footprint 0603_HV
footprint 0603S
pins: 1, 2

## CRCW06036M19FKEA
designator R?  ValueDisplayed: 6.19M  (hidden comment: CRCW06036M19FKEA)
RES, 6.19 M, 1%, 0.1 W, 0603; Manufacturer: Vishay-Dale; CompType: Resistor; Value: 6.19Meg; Res_ohm: 6190000; Value_Code: 6M19; Tolerance_%: 1; Power_W: 0.1; Value2: 0.1W; VDC_V: 75; TempCo: 100 ppm/C; SizeArea_mm2: 1.28; SizeX_mm: 1.6; SizeY_mm: 0.8; EIA_Code: E96; U/M: EA; AEC Category: Q200
signal-integrity model Resistor
simulation model Resistor
footprint 0603
footprint 0603M
footprint 0603L
footprint 0603_HV
footprint 0603S
pins: 1, 2

## CRCW06036M20JNEA
designator R?  ValueDisplayed: 6.2M  (hidden comment: CRCW06036M20JNEA)
RES, 6.2 M, 5%, 0.1 W, 0603; Manufacturer: Vishay-Dale; CompType: Resistor; Value: 6.2Meg; Res_ohm: 6200000; Value_Code: 6M20; Tolerance_%: 5; Power_W: 0.1; Value2: 0.1W; VDC_V: 75; TempCo: 200 ppm/C; SizeArea_mm2: 1.28; SizeX_mm: 1.6; SizeY_mm: 0.8; SizeZ_mm: 1; EIA_Code: E24; U/M: EA; AEC Category: Q200
signal-integrity model Resistor
simulation model Resistor
footprint 0603
footprint 0603M
footprint 0603L
footprint 0603_HV
footprint 0603S
pins: 1, 2

## CRCW06036M34FKEA
designator R?  ValueDisplayed: 6.34M  (hidden comment: CRCW06036M34FKEA)
RES, 6.34 M, 1%, 0.1 W, 0603; Manufacturer: Vishay-Dale; CompType: Resistor; Value: 6.34Meg; Res_ohm: 6340000; Value_Code: 6M34; Tolerance_%: 1; Power_W: 0.1; Value2: 0.1W; VDC_V: 75; TempCo: 100 ppm/C; SizeArea_mm2: 1.28; SizeX_mm: 1.6; SizeY_mm: 0.8; EIA_Code: E96; U/M: EA; AEC Category: Q200
signal-integrity model Resistor
simulation model Resistor
footprint 0603
footprint 0603M
footprint 0603L
footprint 0603_HV
footprint 0603S
pins: 1, 2

## CRCW06036M49FKEA
designator R?  ValueDisplayed: 6.49M  (hidden comment: CRCW06036M49FKEA)
RES, 6.49 M, 1%, 0.1 W, 0603; Manufacturer: Vishay-Dale; CompType: Resistor; Value: 6.49Meg; Res_ohm: 6490000; Value_Code: 6M49; Tolerance_%: 1; Power_W: 0.1; Value2: 0.1W; VDC_V: 75; TempCo: 100 ppm/C; SizeArea_mm2: 1.28; SizeX_mm: 1.6; SizeY_mm: 0.8; EIA_Code: E96; U/M: EA; AEC Category: Q200
signal-integrity model Resistor
simulation model Resistor
footprint 0603
footprint 0603M
footprint 0603L
footprint 0603_HV
footprint 0603S
pins: 1, 2

## CRCW06036M65FKEA
designator R?  ValueDisplayed: 6.65M  (hidden comment: CRCW06036M65FKEA)
RES, 6.65 M, 1%, 0.1 W, 0603; Manufacturer: Vishay-Dale; CompType: Resistor; Value: 6.65Meg; Res_ohm: 6650000; Value_Code: 6M65; Tolerance_%: 1; Power_W: 0.1; Value2: 0.1W; VDC_V: 75; TempCo: 100 ppm/C; SizeArea_mm2: 1.28; SizeX_mm: 1.6; SizeY_mm: 0.8; EIA_Code: E96; U/M: EA; AEC Category: Q200
signal-integrity model Resistor
simulation model Resistor
footprint 0603
footprint 0603M
footprint 0603L
footprint 0603_HV
footprint 0603S
pins: 1, 2

## CRCW06036M80JNEA
designator R?  ValueDisplayed: 6.8M  (hidden comment: CRCW06036M80JNEA)
RES, 6.8 M, 5%, 0.1 W, 0603; Manufacturer: Vishay-Dale; CompType: Resistor; Value: 6.8Meg; Res_ohm: 6800000; Value_Code: 6M80; Tolerance_%: 5; Power_W: 0.1; Value2: 0.1W; VDC_V: 75; TempCo: 200 ppm/C; SizeArea_mm2: 1.28; SizeX_mm: 1.6; SizeY_mm: 0.8; SizeZ_mm: 1; EIA_Code: E24; U/M: EA; AEC Category: Q200
signal-integrity model Resistor
simulation model Resistor
footprint 0603
footprint 0603M
footprint 0603L
footprint 0603_HV
footprint 0603S
pins: 1, 2

## CRCW06036M81FKEA
designator R?  ValueDisplayed: 6.81M  (hidden comment: CRCW06036M81FKEA)
RES, 6.81 M, 1%, 0.1 W, 0603; Manufacturer: Vishay-Dale; CompType: Resistor; Value: 6.81Meg; Res_ohm: 6810000; Value_Code: 6M81; Tolerance_%: 1; Power_W: 0.1; Value2: 0.1W; VDC_V: 75; TempCo: 100 ppm/C; SizeArea_mm2: 1.28; SizeX_mm: 1.6; SizeY_mm: 0.8; EIA_Code: E96; U/M: EA; AEC Category: Q200
signal-integrity model Resistor
simulation model Resistor
footprint 0603
footprint 0603M
footprint 0603L
footprint 0603_HV
footprint 0603S
pins: 1, 2

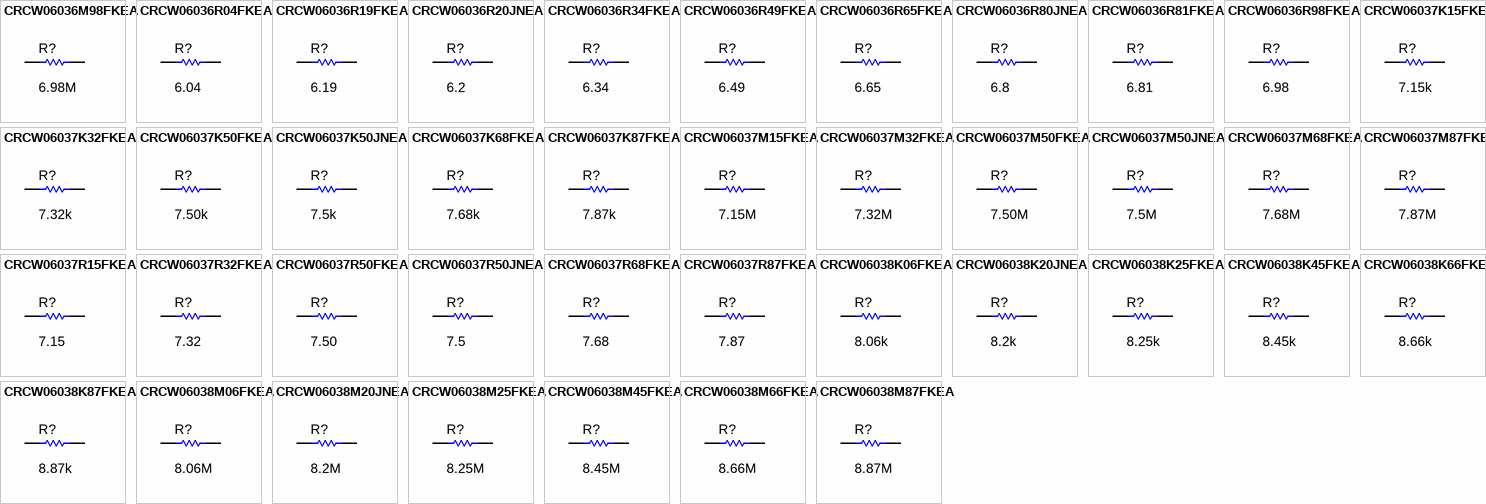
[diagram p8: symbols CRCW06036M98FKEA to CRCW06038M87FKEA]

## CRCW06036M98FKEA
designator R?  ValueDisplayed: 6.98M  (hidden comment: CRCW06036M98FKEA)
RES, 6.98 M, 1%, 0.1 W, 0603; Manufacturer: Vishay-Dale; CompType: Resistor; Value: 6.98Meg; Res_ohm: 6980000; Value_Code: 6M98; Tolerance_%: 1; Power_W: 0.1; Value2: 0.1W; VDC_V: 75; TempCo: 100 ppm/C; SizeArea_mm2: 1.28; SizeX_mm: 1.6; SizeY_mm: 0.8; EIA_Code: E96; U/M: EA; AEC Category: Q200; Green_Lifecycle: Active; Green_REACh: Passed
signal-integrity model Resistor
simulation model Resistor
footprint 0603
footprint 0603M
footprint 0603L
footprint 0603_HV
footprint 0603S
pins: 1, 2

## CRCW06036R04FKEA
designator R?  ValueDisplayed: 6.04  (hidden comment: CRCW06036R04FKEA)
RES, 6.04, 1%, 0.1 W, 0603; Manufacturer: Vishay-Dale; CompType: Resistor; Value: 6.04; Value_Code: 6R04; Tolerance_%: 1; Power_W: 0.1; Value2: 0.1W; VDC_V: 75; TempCo: 100 ppm/C; SizeArea_mm2: 1.28; SizeX_mm: 1.6; SizeY_mm: 0.8; EIA_Code: E96; U/M: EA; AEC Category: Q200; Green_Lifecycle: Active; Green_REACh: Passed
signal-integrity model Resistor
simulation model Resistor
footprint 0603
footprint 0603M
footprint 0603L
footprint 0603_HV
footprint 0603S
pins: 1, 2

## CRCW06036R19FKEA
designator R?  ValueDisplayed: 6.19  (hidden comment: CRCW06036R19FKEA)
RES, 6.19, 1%, 0.1 W, 0603; Manufacturer: Vishay-Dale; CompType: Resistor; Value: 6.19; Value_Code: 6R19; Tolerance_%: 1; Power_W: 0.1; Value2: 0.1W; VDC_V: 75; TempCo: 100 ppm/C; SizeArea_mm2: 1.28; SizeX_mm: 1.6; SizeY_mm: 0.8; EIA_Code: E96; U/M: EA; AEC Category: Q200
signal-integrity model Resistor
simulation model Resistor
footprint 0603
footprint 0603M
footprint 0603L
footprint 0603_HV
footprint 0603S
pins: 1, 2

## CRCW06036R20JNEA
designator R?  ValueDisplayed: 6.2  (hidden comment: CRCW06036R20JNEA)
RES, 6.2, 5%, 0.1 W, 0603; Manufacturer: Vishay-Dale; CompType: Resistor; Value: 6.2; Value_Code: 6R20; Tolerance_%: 5; Power_W: 0.1; Value2: 0.1W; VDC_V: 75; TempCo: 200 ppm/C; SizeArea_mm2: 1.28; SizeX_mm: 1.6; SizeY_mm: 0.8; SizeZ_mm: 1; EIA_Code: E24; U/M: EA; AEC Category: Q200
signal-integrity model Resistor
simulation model Resistor
footprint 0603
footprint 0603M
footprint 0603L
footprint 0603_HV
footprint 0603S
pins: 1, 2

## CRCW06036R34FKEA
designator R?  ValueDisplayed: 6.34  (hidden comment: CRCW06036R34FKEA)
RES, 6.34, 1%, 0.1 W, 0603; Manufacturer: Vishay-Dale; CompType: Resistor; Value: 6.34; Value_Code: 6R34; Tolerance_%: 1; Power_W: 0.1; Value2: 0.1W; VDC_V: 75; TempCo: 100 ppm/C; SizeArea_mm2: 1.28; SizeX_mm: 1.6; SizeY_mm: 0.8; EIA_Code: E96; U/M: EA; AEC Category: Q200
signal-integrity model Resistor
simulation model Resistor
footprint 0603
footprint 0603M
footprint 0603L
footprint 0603_HV
footprint 0603S
pins: 1, 2

## CRCW06036R49FKEA
designator R?  ValueDisplayed: 6.49  (hidden comment: CRCW06036R49FKEA)
RES, 6.49, 1%, 0.1 W, 0603; Manufacturer: Vishay-Dale; CompType: Resistor; Value: 6.49; Value_Code: 6R49; Tolerance_%: 1; Power_W: 0.1; Value2: 0.1W; VDC_V: 75; TempCo: 100 ppm/C; SizeArea_mm2: 1.28; SizeX_mm: 1.6; SizeY_mm: 0.8; EIA_Code: E96; U/M: EA; AEC Category: Q200
signal-integrity model Resistor
simulation model Resistor
footprint 0603
footprint 0603M
footprint 0603L
footprint 0603_HV
footprint 0603S
pins: 1, 2

## CRCW06036R65FKEA
designator R?  ValueDisplayed: 6.65  (hidden comment: CRCW06036R65FKEA)
RES, 6.65, 1%, 0.1 W, 0603; Manufacturer: Vishay-Dale; CompType: Resistor; Value: 6.65; Value_Code: 6R65; Tolerance_%: 1; Power_W: 0.1; Value2: 0.1W; VDC_V: 75; TempCo: 100 ppm/C; SizeArea_mm2: 1.28; SizeX_mm: 1.6; SizeY_mm: 0.8; EIA_Code: E96; U/M: EA; AEC Category: Q200
signal-integrity model Resistor
simulation model Resistor
footprint 0603
footprint 0603M
footprint 0603L
footprint 0603_HV
footprint 0603S
pins: 1, 2

## CRCW06036R80JNEA
designator R?  ValueDisplayed: 6.8  (hidden comment: CRCW06036R80JNEA)
RES, 6.8, 5%, 0.1 W, 0603; Manufacturer: Vishay-Dale; CompType: Resistor; Value: 6.8; Value_Code: 6R80; Tolerance_%: 5; Power_W: 0.1; Value2: 0.1W; VDC_V: 75; TempCo: 200 ppm/C; SizeArea_mm2: 1.28; SizeX_mm: 1.6; SizeY_mm: 0.8; SizeZ_mm: 1; EIA_Code: E24; U/M: EA; AEC Category: Q200; Green_Lifecycle: Active; Green_REACh: Passed
signal-integrity model Resistor
simulation model Resistor
footprint 0603
footprint 0603M
footprint 0603L
footprint 0603_HV
footprint 0603S
pins: 1, 2

## CRCW06036R81FKEA
designator R?  ValueDisplayed: 6.81  (hidden comment: CRCW06036R81FKEA)
RES, 6.81, 1%, 0.1 W, 0603; Manufacturer: Vishay-Dale; CompType: Resistor; Value: 6.81; Value_Code: 6R81; Tolerance_%: 1; Power_W: 0.1; Value2: 0.1W; VDC_V: 75; TempCo: 100 ppm/C; SizeArea_mm2: 1.28; SizeX_mm: 1.6; SizeY_mm: 0.8; EIA_Code: E96; U/M: EA; AEC Category: Q200
signal-integrity model Resistor
simulation model Resistor
footprint 0603
footprint 0603M
footprint 0603L
footprint 0603_HV
footprint 0603S
pins: 1, 2

## CRCW06036R98FKEA
designator R?  ValueDisplayed: 6.98  (hidden comment: CRCW06036R98FKEA)
RES, 6.98, 1%, 0.1 W, 0603; Manufacturer: Vishay-Dale; CompType: Resistor; Value: 6.98; Value_Code: 6R98; Tolerance_%: 1; Power_W: 0.1; Value2: 0.1W; VDC_V: 75; TempCo: 100 ppm/C; SizeArea_mm2: 1.28; SizeX_mm: 1.6; SizeY_mm: 0.8; EIA_Code: E96; U/M: EA; AEC Category: Q200
signal-integrity model Resistor
simulation model Resistor
footprint 0603
footprint 0603M
footprint 0603L
footprint 0603_HV
footprint 0603S
pins: 1, 2

## CRCW06037K15FKEA
designator R?  ValueDisplayed: 7.15k  (hidden comment: CRCW06037K15FKEA)
RES, 7.15 k, 1%, 0.1 W, 0603; Manufacturer: Vishay-Dale; CompType: Resistor; Value: 7.15k; Res_ohm: 7150; Value_Code: 7k15; Tolerance_%: 1; Power_W: 0.1; Value2: 0.1W; VDC_V: 75; TempCo: 100 ppm/C; SizeArea_mm2: 1.28; SizeX_mm: 1.6; SizeY_mm: 0.8; EIA_Code: E96; U/M: EA; AEC Category: Q200; Green_Lifecycle: Active; Green_REACh: Passed
signal-integrity model Resistor
simulation model Resistor
footprint 0603
footprint 0603M
footprint 0603L
footprint 0603_HV
footprint 0603S
pins: 1, 2

## CRCW06037K32FKEA
designator R?  ValueDisplayed: 7.32k  (hidden comment: CRCW06037K32FKEA)
RES, 7.32 k, 1%, 0.1 W, 0603; Manufacturer: Vishay-Dale; CompType: Resistor; Value: 7.32k; Res_ohm: 7320; Value_Code: 7k32; Tolerance_%: 1; Power_W: 0.1; Value2: 0.1W; VDC_V: 75; TempCo: 100 ppm/C; SizeArea_mm2: 1.28; SizeX_mm: 1.6; SizeY_mm: 0.8; EIA_Code: E96; U/M: EA; AEC Category: Q200; Green_Lifecycle: Active; Green_REACh: Passed
signal-integrity model Resistor
simulation model Resistor
footprint 0603
footprint 0603M
footprint 0603L
footprint 0603_HV
footprint 0603S
pins: 1, 2

## CRCW06037K50FKEA
designator R?  ValueDisplayed: 7.50k  (hidden comment: CRCW06037K50FKEA)
RES, 7.50 k, 1%, 0.1 W, 0603; Manufacturer: Vishay-Dale; CompType: Resistor; Value: 7.50k; Res_ohm: 7500; Value_Code: 7k50; Tolerance_%: 1; Power_W: 0.1; Value2: 0.1W; VDC_V: 75; TempCo: 100 ppm/C; SizeArea_mm2: 1.28; SizeX_mm: 1.6; SizeY_mm: 0.8; EIA_Code: E96; U/M: EA; AEC Category: Q200; Green_Lifecycle: Active; Green_REACh: Passed
signal-integrity model Resistor
simulation model Resistor
footprint 0603
footprint 0603M
footprint 0603L
footprint 0603_HV
footprint 0603S
pins: 1, 2

## CRCW06037K50JNEA
designator R?  ValueDisplayed: 7.5k  (hidden comment: CRCW06037K50JNEA)
RES, 7.5 k, 5%, 0.1 W, 0603; Manufacturer: Vishay-Dale; CompType: Resistor; Value: 7.5k; Res_ohm: 7500; Value_Code: 7k50; Tolerance_%: 5; Power_W: 0.1; Value2: 0.1W; VDC_V: 75; TempCo: 200 ppm/C; SizeArea_mm2: 1.28; SizeX_mm: 1.6; SizeY_mm: 0.8; SizeZ_mm: 1; EIA_Code: E24; U/M: EA; AEC Category: Q200; Green_Lifecycle: Active; Green_REACh: Passed
signal-integrity model Resistor
simulation model Resistor
footprint 0603
footprint 0603M
footprint 0603L
footprint 0603_HV
footprint 0603S
pins: 1, 2

## CRCW06037K68FKEA
designator R?  ValueDisplayed: 7.68k  (hidden comment: CRCW06037K68FKEA)
RES, 7.68 k, 1%, 0.1 W, 0603; Manufacturer: Vishay-Dale; CompType: Resistor; Value: 7.68k; Res_ohm: 7680; Value_Code: 7k68; Tolerance_%: 1; Power_W: 0.1; Value2: 0.1W; VDC_V: 75; TempCo: 100 ppm/C; SizeArea_mm2: 1.28; SizeX_mm: 1.6; SizeY_mm: 0.8; EIA_Code: E96; U/M: EA; AEC Category: Q200; Green_Lifecycle: Active; Green_REACh: Passed
signal-integrity model Resistor
simulation model Resistor
footprint 0603
footprint 0603M
footprint 0603L
footprint 0603_HV
footprint 0603S
pins: 1, 2

## CRCW06037K87FKEA
designator R?  ValueDisplayed: 7.87k  (hidden comment: CRCW06037K87FKEA)
RES, 7.87 k, 1%, 0.1 W, 0603; Manufacturer: Vishay-Dale; CompType: Resistor; Value: 7.87k; Res_ohm: 7870; Value_Code: 7k87; Tolerance_%: 1; Power_W: 0.1; Value2: 0.1W; VDC_V: 75; TempCo: 100 ppm/C; SizeArea_mm2: 1.28; SizeX_mm: 1.6; SizeY_mm: 0.8; EIA_Code: E96; U/M: EA; AEC Category: Q200; Green_Lifecycle: Active; Green_REACh: Passed
signal-integrity model Resistor
simulation model Resistor
footprint 0603
footprint 0603M
footprint 0603L
footprint 0603_HV
footprint 0603S
pins: 1, 2

## CRCW06037M15FKEA
designator R?  ValueDisplayed: 7.15M  (hidden comment: CRCW06037M15FKEA)
RES, 7.15 M, 1%, 0.1 W, 0603; Manufacturer: Vishay-Dale; CompType: Resistor; Value: 7.15Meg; Res_ohm: 7150000; Value_Code: 7M15; Tolerance_%: 1; Power_W: 0.1; Value2: 0.1W; VDC_V: 75; TempCo: 100 ppm/C; SizeArea_mm2: 1.28; SizeX_mm: 1.6; SizeY_mm: 0.8; EIA_Code: E96; U/M: EA; AEC Category: Q200
signal-integrity model Resistor
simulation model Resistor
footprint 0603
footprint 0603M
footprint 0603L
footprint 0603_HV
footprint 0603S
pins: 1, 2

## CRCW06037M32FKEA
designator R?  ValueDisplayed: 7.32M  (hidden comment: CRCW06037M32FKEA)
RES, 7.32 M, 1%, 0.1 W, 0603; Manufacturer: Vishay-Dale; CompType: Resistor; Value: 7.32Meg; Res_ohm: 7320000; Value_Code: 7M32; Tolerance_%: 1; Power_W: 0.1; Value2: 0.1W; VDC_V: 75; TempCo: 100 ppm/C; SizeArea_mm2: 1.28; SizeX_mm: 1.6; SizeY_mm: 0.8; EIA_Code: E96; U/M: EA; AEC Category: Q200
signal-integrity model Resistor
simulation model Resistor
footprint 0603
footprint 0603M
footprint 0603L
footprint 0603_HV
footprint 0603S
pins: 1, 2

## CRCW06037M50FKEA
designator R?  ValueDisplayed: 7.50M  (hidden comment: CRCW06037M50FKEA)
RES, 7.50 M, 1%, 0.1 W, 0603; Manufacturer: Vishay-Dale; CompType: Resistor; Value: 7.50Meg; Res_ohm: 7500000; Value_Code: 7M50; Tolerance_%: 1; Power_W: 0.1; Value2: 0.1W; VDC_V: 75; TempCo: 100 ppm/C; SizeArea_mm2: 1.28; SizeX_mm: 1.6; SizeY_mm: 0.8; EIA_Code: E96; U/M: EA; AEC Category: Q200; Green_Lifecycle: Active; Green_REACh: Passed
signal-integrity model Resistor
simulation model Resistor
footprint 0603
footprint 0603M
footprint 0603L
footprint 0603_HV
footprint 0603S
pins: 1, 2

## CRCW06037M50JNEA
designator R?  ValueDisplayed: 7.5M  (hidden comment: CRCW06037M50JNEA)
RES, 7.5 M, 5%, 0.1 W, 0603; Manufacturer: Vishay-Dale; CompType: Resistor; Value: 7.5Meg; Res_ohm: 7500000; Value_Code: 7M50; Tolerance_%: 5; Power_W: 0.1; Value2: 0.1W; VDC_V: 75; TempCo: 200 ppm/C; SizeArea_mm2: 1.28; SizeX_mm: 1.6; SizeY_mm: 0.8; SizeZ_mm: 1; EIA_Code: E24; U/M: EA; AEC Category: Q200
signal-integrity model Resistor
simulation model Resistor
footprint 0603
footprint 0603M
footprint 0603L
footprint 0603_HV
footprint 0603S
pins: 1, 2

## CRCW06037M68FKEA
designator R?  ValueDisplayed: 7.68M  (hidden comment: CRCW06037M68FKEA)
RES, 7.68 M, 1%, 0.1 W, 0603; Manufacturer: Vishay-Dale; CompType: Resistor; Value: 7.68Meg; Res_ohm: 7680000; Value_Code: 7M68; Tolerance_%: 1; Power_W: 0.1; Value2: 0.1W; VDC_V: 75; TempCo: 100 ppm/C; SizeArea_mm2: 1.28; SizeX_mm: 1.6; SizeY_mm: 0.8; EIA_Code: E96; U/M: EA; AEC Category: Q200
signal-integrity model Resistor
simulation model Resistor
footprint 0603
footprint 0603M
footprint 0603L
footprint 0603_HV
footprint 0603S
pins: 1, 2

## CRCW06037M87FKEA
designator R?  ValueDisplayed: 7.87M  (hidden comment: CRCW06037M87FKEA)
RES, 7.87 M, 1%, 0.1 W, 0603; Manufacturer: Vishay-Dale; CompType: Resistor; Value: 7.87Meg; Res_ohm: 7870000; Value_Code: 7M87; Tolerance_%: 1; Power_W: 0.1; Value2: 0.1W; VDC_V: 75; TempCo: 100 ppm/C; SizeArea_mm2: 1.28; SizeX_mm: 1.6; SizeY_mm: 0.8; EIA_Code: E96; U/M: EA; AEC Category: Q200
signal-integrity model Resistor
simulation model Resistor
footprint 0603
footprint 0603M
footprint 0603L
footprint 0603_HV
footprint 0603S
pins: 1, 2

## CRCW06037R15FKEA
designator R?  ValueDisplayed: 7.15  (hidden comment: CRCW06037R15FKEA)
RES, 7.15, 1%, 0.1 W, 0603; Manufacturer: Vishay-Dale; CompType: Resistor; Value: 7.15; Value_Code: 7R15; Tolerance_%: 1; Power_W: 0.1; Value2: 0.1W; VDC_V: 75; TempCo: 100 ppm/C; SizeArea_mm2: 1.28; SizeX_mm: 1.6; SizeY_mm: 0.8; EIA_Code: E96; U/M: EA; AEC Category: Q200
signal-integrity model Resistor
simulation model Resistor
footprint 0603
footprint 0603M
footprint 0603L
footprint 0603_HV
footprint 0603S
pins: 1, 2

## CRCW06037R32FKEA
designator R?  ValueDisplayed: 7.32  (hidden comment: CRCW06037R32FKEA)
RES, 7.32, 1%, 0.1 W, 0603; Manufacturer: Vishay-Dale; CompType: Resistor; Value: 7.32; Value_Code: 7R32; Tolerance_%: 1; Power_W: 0.1; Value2: 0.1W; VDC_V: 75; TempCo: 100 ppm/C; SizeArea_mm2: 1.28; SizeX_mm: 1.6; SizeY_mm: 0.8; EIA_Code: E96; U/M: EA; AEC Category: Q200
signal-integrity model Resistor
simulation model Resistor
footprint 0603
footprint 0603M
footprint 0603L
footprint 0603_HV
footprint 0603S
pins: 1, 2

## CRCW06037R50FKEA
designator R?  ValueDisplayed: 7.50  (hidden comment: CRCW06037R50FKEA)
RES, 7.50, 1%, 0.1 W, 0603; Manufacturer: Vishay-Dale; CompType: Resistor; Value: 7.50; Res_ohm: 7.5; Value_Code: 7R50; Tolerance_%: 1; Power_W: 0.1; Value2: 0.1W; VDC_V: 75; TempCo: 100 ppm/C; SizeArea_mm2: 1.28; SizeX_mm: 1.6; SizeY_mm: 0.8; EIA_Code: E96; U/M: EA; AEC Category: Q200
signal-integrity model Resistor
simulation model Resistor
footprint 0603
footprint 0603M
footprint 0603L
footprint 0603_HV
footprint 0603S
pins: 1, 2

## CRCW06037R50JNEA
designator R?  ValueDisplayed: 7.5  (hidden comment: CRCW06037R50JNEA)
RES, 7.5, 5%, 0.1 W, 0603; Manufacturer: Vishay-Dale; CompType: Resistor; Value: 7.5; Value_Code: 7R50; Tolerance_%: 5; Power_W: 0.1; Value2: 0.1W; VDC_V: 75; TempCo: 200 ppm/C; SizeArea_mm2: 1.28; SizeX_mm: 1.6; SizeY_mm: 0.8; SizeZ_mm: 1; EIA_Code: E24; U/M: EA; AEC Category: Q200
signal-integrity model Resistor
simulation model Resistor
footprint 0603
footprint 0603M
footprint 0603L
footprint 0603_HV
footprint 0603S
pins: 1, 2

## CRCW06037R68FKEA
designator R?  ValueDisplayed: 7.68  (hidden comment: CRCW06037R68FKEA)
RES, 7.68, 1%, 0.1 W, 0603; Manufacturer: Vishay-Dale; CompType: Resistor; Value: 7.68; Value_Code: 7R68; Tolerance_%: 1; Power_W: 0.1; Value2: 0.1W; VDC_V: 75; TempCo: 100 ppm/C; SizeArea_mm2: 1.28; SizeX_mm: 1.6; SizeY_mm: 0.8; EIA_Code: E96; U/M: EA; AEC Category: Q200
signal-integrity model Resistor
simulation model Resistor
footprint 0603
footprint 0603M
footprint 0603L
footprint 0603_HV
footprint 0603S
pins: 1, 2

## CRCW06037R87FKEA
designator R?  ValueDisplayed: 7.87  (hidden comment: CRCW06037R87FKEA)
RES, 7.87, 1%, 0.1 W, 0603; Manufacturer: Vishay-Dale; CompType: Resistor; Value: 7.87; Value_Code: 7R87; Tolerance_%: 1; Power_W: 0.1; Value2: 0.1W; VDC_V: 75; TempCo: 100 ppm/C; SizeArea_mm2: 1.28; SizeX_mm: 1.6; SizeY_mm: 0.8; EIA_Code: E96; U/M: EA; AEC Category: Q200
signal-integrity model Resistor
simulation model Resistor
footprint 0603
footprint 0603M
footprint 0603L
footprint 0603_HV
footprint 0603S
pins: 1, 2

## CRCW06038K06FKEA
designator R?  ValueDisplayed: 8.06k  (hidden comment: CRCW06038K06FKEA)
RES, 8.06 k, 1%, 0.1 W, 0603; Manufacturer: Vishay-Dale; CompType: Resistor; Value: 8.06k; Res_ohm: 8060; Value_Code: 8k06; Tolerance_%: 1; Power_W: 0.1; Value2: 0.1W; VDC_V: 75; TempCo: 100 ppm/C; SizeArea_mm2: 1.28; SizeX_mm: 1.6; SizeY_mm: 0.8; EIA_Code: E96; U/M: EA; AEC Category: Q200; Green_Lifecycle: Active; Green_REACh: Passed
signal-integrity model Resistor
simulation model Resistor
footprint 0603
footprint 0603M
footprint 0603L
footprint 0603_HV
footprint 0603S
pins: 1, 2

## CRCW06038K20JNEA
designator R?  ValueDisplayed: 8.2k  (hidden comment: CRCW06038K20JNEA)
RES, 8.2 k, 5%, 0.1 W, 0603; Manufacturer: Vishay-Dale; CompType: Resistor; Value: 8.2k; Res_ohm: 8200; Value_Code: 8k20; Tolerance_%: 5; Power_W: 0.1; Value2: 0.1W; VDC_V: 75; TempCo: 200 ppm/C; SizeArea_mm2: 1.28; SizeX_mm: 1.6; SizeY_mm: 0.8; SizeZ_mm: 1; EIA_Code: E24; U/M: EA; AEC Category: Q200; Green_Lifecycle: Active; Green_REACh: Passed
signal-integrity model Resistor
simulation model Resistor
footprint 0603
footprint 0603M
footprint 0603L
footprint 0603_HV
footprint 0603S
pins: 1, 2

## CRCW06038K25FKEA
designator R?  ValueDisplayed: 8.25k  (hidden comment: CRCW06038K25FKEA)
RES, 8.25 k, 1%, 0.1 W, 0603; Manufacturer: Vishay-Dale; CompType: Resistor; Value: 8.25k; Res_ohm: 8250; Value_Code: 8k25; Tolerance_%: 1; Power_W: 0.1; Value2: 0.1W; VDC_V: 75; TempCo: 100 ppm/C; SizeArea_mm2: 1.28; SizeX_mm: 1.6; SizeY_mm: 0.8; EIA_Code: E96; U/M: EA; AEC Category: Q200; Green_Lifecycle: Active; Green_REACh: Passed
signal-integrity model Resistor
simulation model Resistor
footprint 0603
footprint 0603M
footprint 0603L
footprint 0603_HV
footprint 0603S
pins: 1, 2

## CRCW06038K45FKEA
designator R?  ValueDisplayed: 8.45k  (hidden comment: CRCW06038K45FKEA)
RES, 8.45 k, 1%, 0.1 W, 0603; Manufacturer: Vishay-Dale; CompType: Resistor; Value: 8.45k; Res_ohm: 8450; Value_Code: 8k45; Tolerance_%: 1; Power_W: 0.1; Value2: 0.1W; VDC_V: 75; TempCo: 100 ppm/C; SizeArea_mm2: 1.28; SizeX_mm: 1.6; SizeY_mm: 0.8; EIA_Code: E96; U/M: EA; AEC Category: Q200
signal-integrity model Resistor
simulation model Resistor
footprint 0603
footprint 0603M
footprint 0603L
footprint 0603_HV
footprint 0603S
pins: 1, 2

## CRCW06038K66FKEA
designator R?  ValueDisplayed: 8.66k  (hidden comment: CRCW06038K66FKEA)
RES, 8.66 k, 1%, 0.1 W, 0603; Manufacturer: Vishay-Dale; CompType: Resistor; Value: 8.66k; Res_ohm: 8660; Value_Code: 8k66; Tolerance_%: 1; Power_W: 0.1; Value2: 0.1W; VDC_V: 75; TempCo: 100 ppm/C; SizeArea_mm2: 1.28; SizeX_mm: 1.6; SizeY_mm: 0.8; EIA_Code: E96; U/M: EA; AEC Category: Q200; Green_Lifecycle: Active; Green_REACh: Passed
signal-integrity model Resistor
simulation model Resistor
footprint 0603
footprint 0603M
footprint 0603L
footprint 0603_HV
footprint 0603S
pins: 1, 2

## CRCW06038K87FKEA
designator R?  ValueDisplayed: 8.87k  (hidden comment: CRCW06038K87FKEA)
RES, 8.87 k, 1%, 0.1 W, 0603; Manufacturer: Vishay-Dale; CompType: Resistor; Value: 8.87k; Res_ohm: 8870; Value_Code: 8k87; Tolerance_%: 1; Power_W: 0.1; Value2: 0.1W; VDC_V: 75; TempCo: 100 ppm/C; SizeArea_mm2: 1.28; SizeX_mm: 1.6; SizeY_mm: 0.8; EIA_Code: E96; U/M: EA; AEC Category: Q200; Green_Lifecycle: Active; Green_REACh: Passed
signal-integrity model Resistor
simulation model Resistor
footprint 0603
footprint 0603M
footprint 0603L
footprint 0603_HV
footprint 0603S
pins: 1, 2

## CRCW06038M06FKEA
designator R?  ValueDisplayed: 8.06M  (hidden comment: CRCW06038M06FKEA)
RES, 8.06 M, 1%, 0.1 W, 0603; Manufacturer: Vishay-Dale; CompType: Resistor; Value: 8.06Meg; Res_ohm: 8060000; Value_Code: 8M06; Tolerance_%: 1; Power_W: 0.1; Value2: 0.1W; VDC_V: 75; TempCo: 100 ppm/C; SizeArea_mm2: 1.28; SizeX_mm: 1.6; SizeY_mm: 0.8; EIA_Code: E96; U/M: EA; AEC Category: Q200
signal-integrity model Resistor
simulation model Resistor
footprint 0603
footprint 0603M
footprint 0603L
footprint 0603_HV
footprint 0603S
pins: 1, 2

## CRCW06038M20JNEA
designator R?  ValueDisplayed: 8.2M  (hidden comment: CRCW06038M20JNEA)
RES, 8.2 M, 5%, 0.1 W, 0603; Manufacturer: Vishay-Dale; CompType: Resistor; Value: 8.2Meg; Res_ohm: 8200000; Value_Code: 8M20; Tolerance_%: 5; Power_W: 0.1; Value2: 0.1W; VDC_V: 75; TempCo: 200 ppm/C; SizeArea_mm2: 1.28; SizeX_mm: 1.6; SizeY_mm: 0.8; SizeZ_mm: 1; EIA_Code: E24; U/M: EA; AEC Category: Q200
signal-integrity model Resistor
simulation model Resistor
footprint 0603
footprint 0603M
footprint 0603L
footprint 0603_HV
footprint 0603S
pins: 1, 2

## CRCW06038M25FKEA
designator R?  ValueDisplayed: 8.25M  (hidden comment: CRCW06038M25FKEA)
RES, 8.25 M, 1%, 0.1 W, 0603; Manufacturer: Vishay-Dale; CompType: Resistor; Value: 8.25Meg; Res_ohm: 8250000; Value_Code: 8M25; Tolerance_%: 1; Power_W: 0.1; Value2: 0.1W; VDC_V: 75; TempCo: 100 ppm/C; SizeArea_mm2: 1.28; SizeX_mm: 1.6; SizeY_mm: 0.8; EIA_Code: E96; U/M: EA; AEC Category: Q200
signal-integrity model Resistor
simulation model Resistor
footprint 0603
footprint 0603M
footprint 0603L
footprint 0603_HV
footprint 0603S
pins: 1, 2

## CRCW06038M45FKEA
designator R?  ValueDisplayed: 8.45M  (hidden comment: CRCW06038M45FKEA)
RES, 8.45 M, 1%, 0.1 W, 0603; Manufacturer: Vishay-Dale; CompType: Resistor; Value: 8.45Meg; Res_ohm: 8450000; Value_Code: 8M45; Tolerance_%: 1; Power_W: 0.1; Value2: 0.1W; VDC_V: 75; TempCo: 100 ppm/C; SizeArea_mm2: 1.28; SizeX_mm: 1.6; SizeY_mm: 0.8; EIA_Code: E96; U/M: EA; AEC Category: Q200
signal-integrity model Resistor
simulation model Resistor
footprint 0603
footprint 0603M
footprint 0603L
footprint 0603_HV
footprint 0603S
pins: 1, 2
